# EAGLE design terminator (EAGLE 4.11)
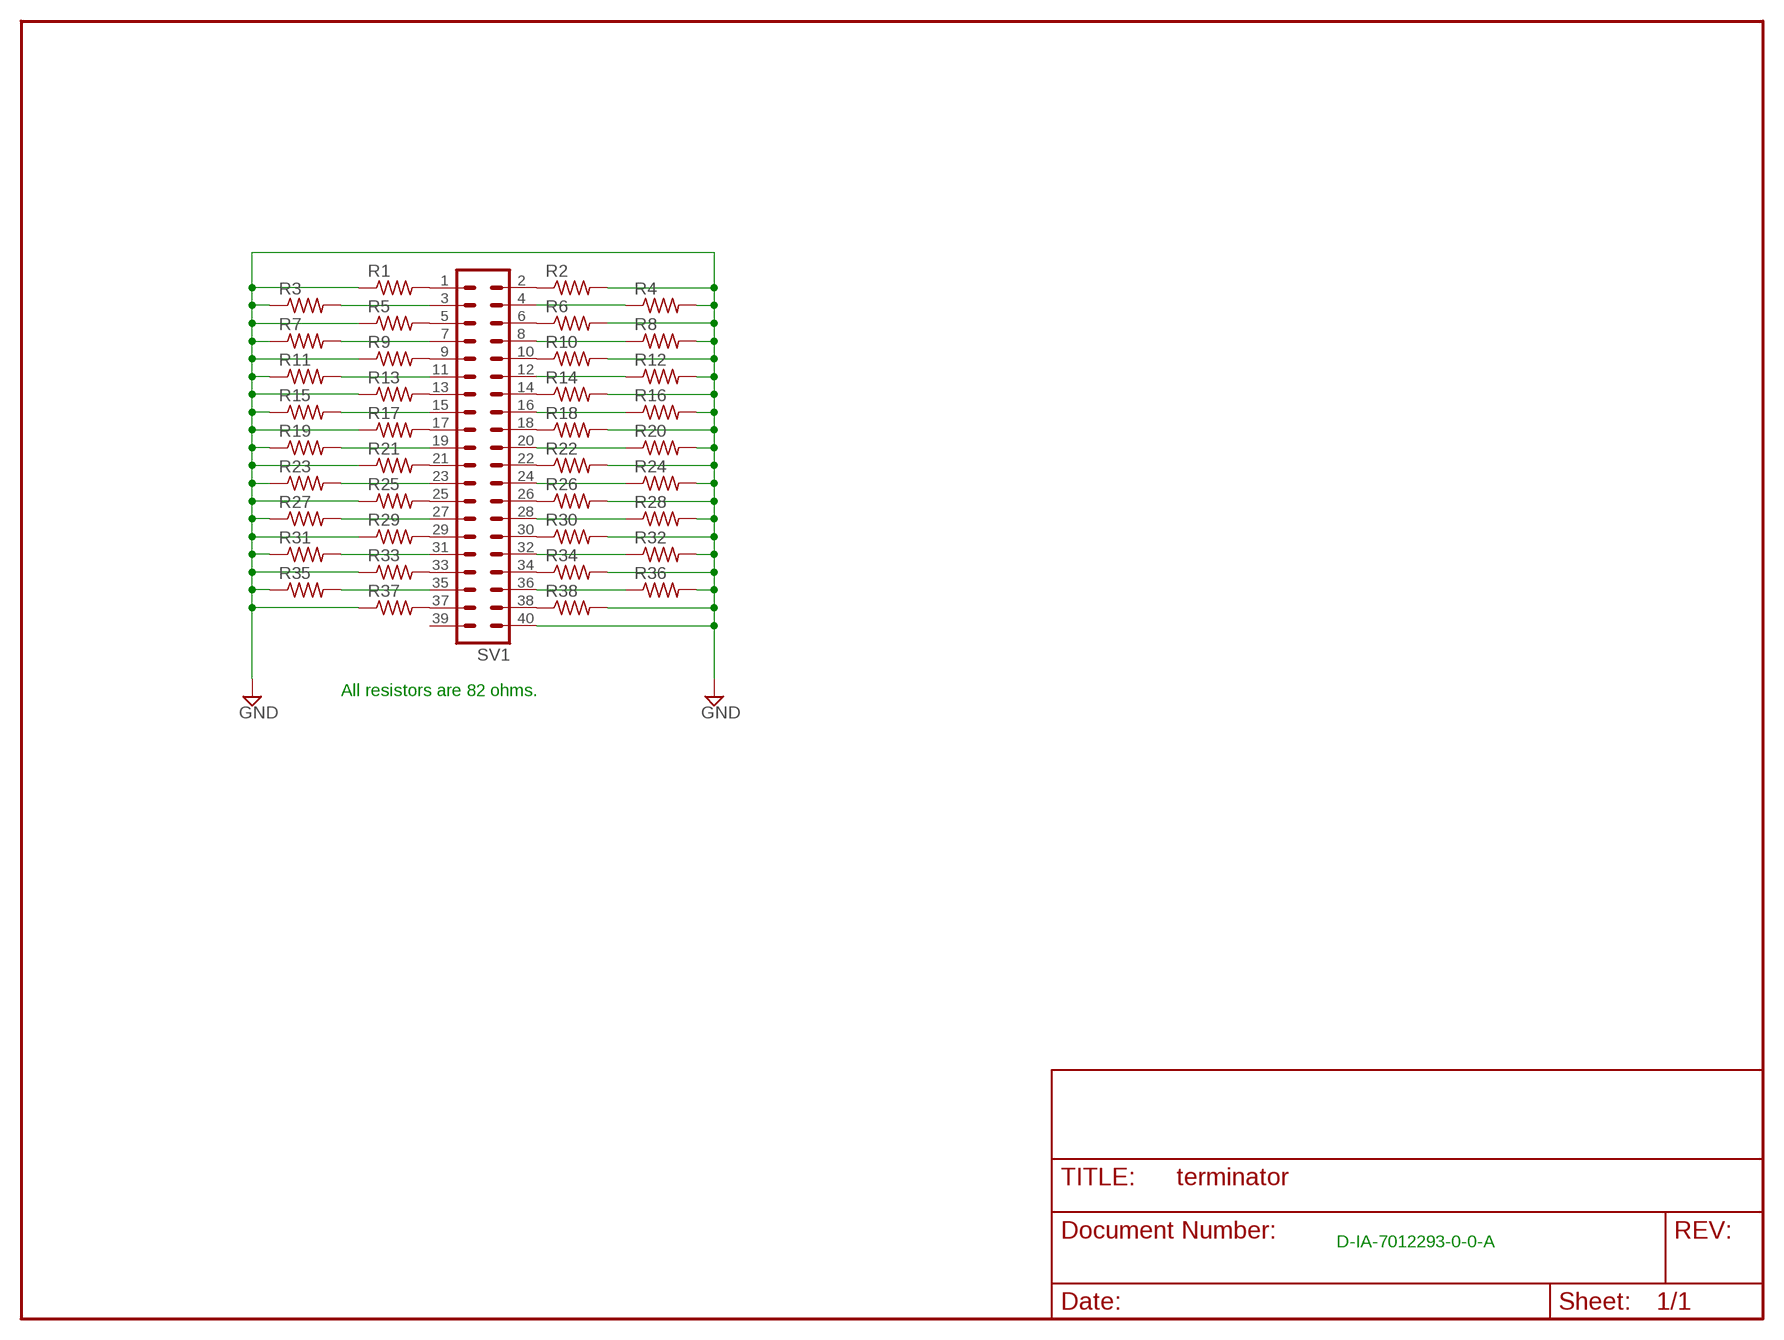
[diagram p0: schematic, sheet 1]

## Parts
R1  R-US_M0805  [M0805]
R2  R-US_M0805  [M0805]
R3  R-US_M0805  [M0805]
R4  R-US_M0805  [M0805]
R5  R-US_M0805  [M0805]
R6  R-US_M0805  [M0805]
R7  R-US_M0805  [M0805]
R8  R-US_M0805  [M0805]
R9  R-US_M0805  [M0805]
R10  R-US_M0805  [M0805]
R11  R-US_M0805  [M0805]
R12  R-US_M0805  [M0805]
R13  R-US_M0805  [M0805]
R14  R-US_M0805  [M0805]
R15  R-US_M0805  [M0805]
R16  R-US_M0805  [M0805]
R17  R-US_M0805  [M0805]
R18  R-US_M0805  [M0805]
R19  R-US_M0805  [M0805]
R20  R-US_M0805  [M0805]
R21  R-US_M0805  [M0805]
R22  R-US_M0805  [M0805]
R23  R-US_M0805  [M0805]
R24  R-US_M0805  [M0805]
R25  R-US_M0805  [M0805]
R26  R-US_M0805  [M0805]
R27  R-US_M0805  [M0805]
R28  R-US_M0805  [M0805]
R29  R-US_M0805  [M0805]
R30  R-US_M0805  [M0805]
R31  R-US_M0805  [M0805]
R32  R-US_M0805  [M0805]
R33  R-US_M0805  [M0805]
R34  R-US_M0805  [M0805]
R35  R-US_M0805  [M0805]
R36  R-US_M0805  [M0805]
R37  R-US_M0805  [M0805]
R38  R-US_M0805  [M0805]
SV1  MA20-2  [MA20-2]

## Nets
GND: R1.1 R2.2 R3.1 R4.2 R5.1 R6.2 R7.1 R8.2 R9.1 R10.2 R11.1 R12.2 R13.1 R14.2 R15.1 R16.2 R17.1 R18.2 R19.1 R20.2 R21.1 R22.2 R23.1 R24.2 R25.1 R26.2 R27.1 R28.2 R29.1 R30.2 R31.1 R32.2 R33.1 R34.2 R35.1 R36.2 R37.1 R38.2 SV1.40
N$1: R1.2 SV1.1
N$2: R2.1 SV1.2
N$3: R5.2 SV1.5
N$4: R6.1 SV1.6
N$5: R9.2 SV1.9
N$6: R10.1 SV1.10
N$7: R13.2 SV1.13
N$8: R14.1 SV1.14
N$9: R17.2 SV1.17
N$10: R18.1 SV1.18
N$11: R21.2 SV1.21
N$12: R22.1 SV1.22
N$13: R25.2 SV1.25
N$14: R26.1 SV1.26
N$15: R29.2 SV1.29
N$16: R30.1 SV1.30
N$17: R33.2 SV1.33
N$18: R34.1 SV1.34
N$19: R37.2 SV1.37
N$20: R38.1 SV1.38
N$21: R3.2 SV1.3
N$22: R7.2 SV1.7
N$23: R11.2 SV1.11
N$24: R15.2 SV1.15
N$25: R19.2 SV1.19
N$26: R23.2 SV1.23
N$27: R27.2 SV1.27
N$28: R31.2 SV1.31
N$29: R35.2 SV1.35
N$30: R36.1 SV1.36
N$31: R32.1 SV1.32
N$32: R28.1 SV1.28
N$33: R24.1 SV1.24
N$34: R20.1 SV1.20
N$35: R16.1 SV1.16
N$36: R12.1 SV1.12
N$37: R8.1 SV1.8
N$38: R4.1 SV1.4
Unconnected: SV1.39

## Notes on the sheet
- All resistors are 82 ohms.
- D-IA-7012293-0-0-A

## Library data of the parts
R1-R38 = rcl:R-US_: RESISTOR, American symbol
SV1 = con-lstb:MA20-2: PIN HEADER

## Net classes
0 default: width 0.508 mm

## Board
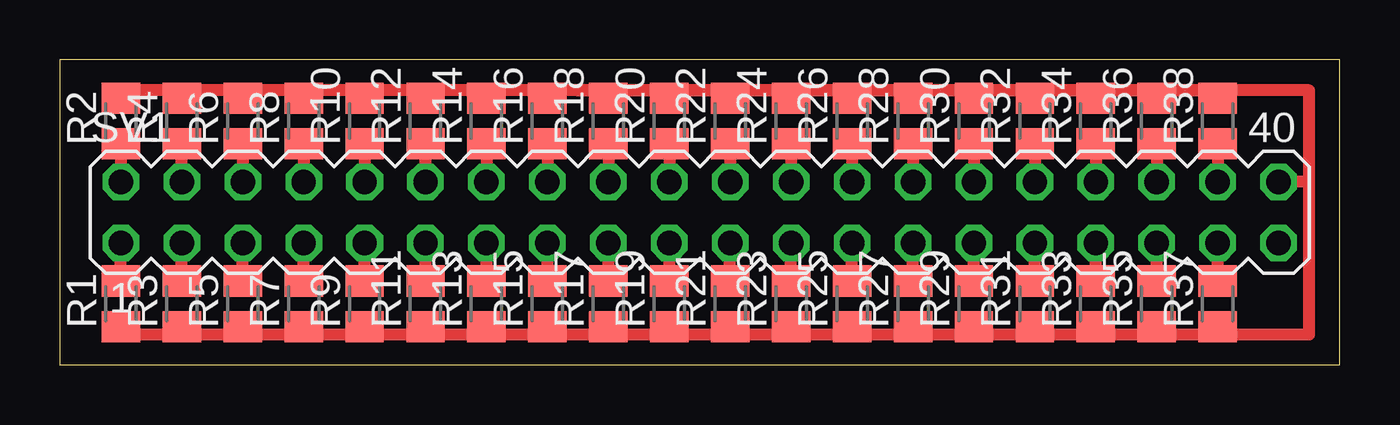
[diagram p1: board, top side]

Size 53.34 x 12.7 mm. Coordinates in mm from the lower left corner, seen from the top.
Outline: 0,0 53.34,0 53.34,12.7 0,12.7 0,0
Copper layers (1*16): Top 0.035mm / dielectric 1.5mm / Bottom 0.035mm
Design rules "custompcb": minimum track width 10mil, minimum drill 24mil, track to track 8mil, track to pad 8mil, pad to pad 8mil, via to via 8mil, smd to smd 0mil, copper to edge 25mil, drill to drill 8mil, minimum pad ring 10mil, minimum via ring 8mil, stop-mask expansion 4mil, vias tented up to drill 0mil, thermal gap 10mil

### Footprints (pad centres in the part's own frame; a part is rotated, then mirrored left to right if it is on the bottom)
M0805 = smd 1.3 x 1.6: 1 -0.95,0; 2 0.95,0
MA20-2 = drill 1.016 octagon: 1 -24.13,-1.27; 2 -24.13,1.27; 3 -21.59,-1.27; 4 -21.59,1.27; 5 -19.05,-1.27; 6 -19.05,1.27; 7 -16.51,-1.27; 8 -16.51,1.27; 9 -13.97,-1.27; 10 -13.97,1.27; 11 -11.43,-1.27; 12 -11.43,1.27; 13 -8.89,-1.27; 14 -8.89,1.27; 15 -6.35,-1.27; 16 -6.35,1.27; 17 -3.81,-1.27; 18 -3.81,1.27; 19 -1.27,-1.27; 20 -1.27,1.27; 21 1.27,-1.27; 22 1.27,1.27; 23 3.81,-1.27; 24 3.81,1.27; 25 6.35,-1.27; 26 6.35,1.27; 27 8.89,-1.27; 28 8.89,1.27; 29 11.43,-1.27; 30 11.43,1.27; 31 13.97,-1.27; 32 13.97,1.27; 33 16.51,-1.27; 34 16.51,1.27; 35 19.05,-1.27; 36 19.05,1.27; 37 21.59,-1.27; 38 21.59,1.27; 39 24.13,-1.27; 40 24.13,1.27

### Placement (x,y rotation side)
R1  2.54,2.54 90 top
R2  2.54,10.16 90 top
R3  5.08,2.54 90 top
R4  5.08,10.16 90 top
R5  7.62,2.54 90 top
R6  7.62,10.16 90 top
R7  10.16,2.54 90 top
R8  10.16,10.16 90 top
R9  12.7,2.54 90 top
R10  12.7,10.16 90 top
R11  15.24,2.54 90 top
R12  15.24,10.16 90 top
R13  17.78,2.54 90 top
R14  17.78,10.16 90 top
R15  20.32,2.54 90 top
R16  20.32,10.16 90 top
R17  22.86,2.54 90 top
R18  22.86,10.16 90 top
R19  25.4,2.54 90 top
R20  25.4,10.16 90 top
R21  27.94,2.54 90 top
R22  27.94,10.16 90 top
R23  30.48,2.54 90 top
R24  30.48,10.16 90 top
R25  33.02,2.54 90 top
R26  33.02,10.16 90 top
R27  35.56,2.54 90 top
R28  35.56,10.16 90 top
R29  38.1,2.54 90 top
R30  38.1,10.16 90 top
R31  40.64,2.54 90 top
R32  40.64,10.16 90 top
R33  43.18,2.54 90 top
R34  43.18,10.16 90 top
R35  45.72,2.54 90 top
R36  45.72,10.16 90 top
R37  48.26,2.54 90 top
R38  48.26,10.16 90 top
SV1  26.67,6.35 0 top

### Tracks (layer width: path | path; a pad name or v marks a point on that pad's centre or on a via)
GND
  Top 0.508: R1.1 3.17,1.27 4.45,1.27 R3.1 5.71,1.27 6.99,1.27 R5.1 8.26,1.27 9.53,1.27 R7.1 10.79,1.27 12.06,1.27 R9.1 13.34,1.27 14.61,1.27 R11.1 15.88,1.27 17.14,1.27 R13.1 18.41,1.27 19.68,1.27 R15.1 20.95,1.27 21.59,1.27 | 21.59,1.27 22.23,1.27 R17.1 23.5,1.27 24.77,1.27 R19.1 26.04,1.27 27.3,1.27 R21.1 28.57,1.27 29.84,1.27 R23.1 31.11,1.27 32.38,1.27 R25.1 33.66,1.27 34.92,1.27 R27.1 36.2,1.27 37.47,1.27 R29.1 38.73,1.27 40.01,1.27 R31.1 41.27,1.27 42.55,1.27 R33.1 43.81,1.27 45.09,1.27 R35.1 46.35,1.27 47.62,1.27 R37.1 | R2.2 3.17,11.43 4.45,11.43 R4.2 5.71,11.43 6.99,11.43 R6.2 8.26,11.43 9.53,11.43 R8.2 10.79,11.43 12.06,11.43 R10.2 13.34,11.43 14.61,11.43 R12.2 15.88,11.43 17.14,11.43 R14.2 18.41,11.43 19.68,11.43 R16.2 20.95,11.43 21.59,11.43 | 21.59,11.43 22.23,11.43 R18.2 23.5,11.43 24.77,11.43 R20.2 26.04,11.43 27.3,11.43 R22.2 28.57,11.43 29.84,11.43 R24.2 31.11,11.43 32.38,11.43 R26.2 33.66,11.43 34.92,11.43 R28.2 36.2,11.43 37.47,11.43 R30.2 38.73,11.43 40.01,11.43 R32.2 41.27,11.43 42.55,11.43 R34.2 43.81,11.43 45.09,11.43 R36.2 46.35,11.43 47.62,11.43 R38.2 | 21.59,1.27 52.07,1.27 52.07,7.62 | 52.07,7.62 52.07,11.43 21.59,11.43 | 52.07,7.62 51.44,7.62 SV1.40
N$1
  Top 0.508: R1.2 2.54,3.81 2.54,4.45 SV1.1
N$2
  Top 0.508: R2.1 2.54,8.89 2.54,8.26 SV1.2
N$3
  Top 0.508: R5.2 7.62,3.81 7.62,4.45 SV1.5
N$4
  Top 0.508: R6.1 7.62,8.89 7.62,8.26 SV1.6
N$5
  Top 0.508: R9.2 12.7,3.81 12.7,4.45 SV1.9
N$6
  Top 0.508: R10.1 12.7,8.89 12.7,8.26 SV1.10
N$7
  Top 0.508: R13.2 17.78,3.81 17.78,4.45 SV1.13
N$8
  Top 0.508: R14.1 17.78,8.89 17.78,8.26 SV1.14
N$9
  Top 0.508: R17.2 22.86,3.81 22.86,4.45 SV1.17
N$10
  Top 0.508: R18.1 22.86,8.89 22.86,8.26 SV1.18
N$11
  Top 0.508: R21.2 27.94,3.81 27.94,4.45 SV1.21
N$12
  Top 0.508: R22.1 27.94,8.89 27.94,8.26 SV1.22
N$13
  Top 0.508: R25.2 33.02,3.81 33.02,4.45 SV1.25
N$14
  Top 0.508: R26.1 33.02,8.89 33.02,8.26 SV1.26
N$15
  Top 0.508: R29.2 38.1,3.81 38.1,4.45 SV1.29
N$16
  Top 0.508: R30.1 38.1,8.89 38.1,8.26 SV1.30
N$17
  Top 0.508: R33.2 43.18,3.81 43.18,4.45 SV1.33
N$18
  Top 0.508: R34.1 43.18,8.89 43.18,8.26 SV1.34
N$19
  Top 0.508: R37.2 48.26,3.81 48.26,4.45 SV1.37
N$20
  Top 0.508: R38.1 48.26,8.89 48.26,8.26 SV1.38
N$21
  Top 0.508: R3.2 5.08,3.81 5.08,4.45 SV1.3
N$22
  Top 0.508: R7.2 10.16,3.81 10.16,4.45 SV1.7
N$23
  Top 0.508: R11.2 15.24,3.81 15.24,4.45 SV1.11
N$24
  Top 0.508: R15.2 20.32,3.81 20.32,4.45 SV1.15
N$25
  Top 0.508: R19.2 25.4,3.81 25.4,4.45 SV1.19
N$26
  Top 0.508: R23.2 30.48,3.81 30.48,4.45 SV1.23
N$27
  Top 0.508: R27.2 35.56,3.81 35.56,4.45 SV1.27
N$28
  Top 0.508: R31.2 40.64,3.81 40.64,4.45 SV1.31
N$29
  Top 0.508: R35.2 45.72,3.81 45.72,4.45 SV1.35
N$30
  Top 0.508: R36.1 45.72,8.89 45.72,8.26 SV1.36
N$31
  Top 0.508: R32.1 40.64,8.89 40.64,8.26 SV1.32
N$32
  Top 0.508: R28.1 35.56,8.89 35.56,8.26 SV1.28
N$33
  Top 0.508: R24.1 30.48,8.89 30.48,8.26 SV1.24
N$34
  Top 0.508: R20.1 25.4,8.89 25.4,8.26 SV1.20
N$35
  Top 0.508: R16.1 20.32,8.89 20.32,8.26 SV1.16
N$36
  Top 0.508: R12.1 15.24,8.89 15.24,8.26 SV1.12
N$37
  Top 0.508: R8.1 10.16,8.89 10.16,8.26 SV1.8
N$38
  Top 0.508: R4.1 5.08,8.89 5.08,8.26 SV1.4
